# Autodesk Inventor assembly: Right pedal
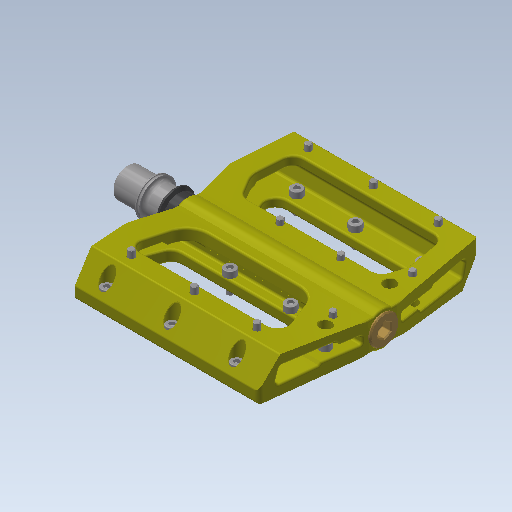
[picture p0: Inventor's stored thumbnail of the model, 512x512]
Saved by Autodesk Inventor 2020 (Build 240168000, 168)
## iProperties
Created: 2017-10
Part Number: Right pedal
Material: Ogólny
Document SubType Name: Assembly
Designer: Tomasz
Sending System: SolidWorks 2017
Last Author: Tomasz
Last Saved: 2017-11-20
Author: Tomasz
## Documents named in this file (3)
- C:\Users\bruno\Documents\1-Cours-2020-21\1STI2D-2020-21\IT\6. Antivol\Inventor-Antivol\INVENTOR 2018_Steel Hardtail B+\Right pedal.iam
- C:\Users\bruno\Documents\1-Cours-2020-21\1STI2D-2020-21\IT\6. Antivol\Inventor-Antivol\INVENTOR 2018_Steel Hardtail B+\Kopia Right pedal.iam^Right pedal.iam
- C:\Users\bruno\Documents\1-Cours-2020-21\1STI2D-2020-21\IT\6. Antivol\Inventor-Antivol\INVENTOR 2018_Steel Hardtail B+\686-2RS bearing.iam
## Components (3 placed, 2 different names)
1. Kopia Right pedal.iam^Right pedal:1 [sub-assembly]
2. 686-2RS bearing:1 [sub-assembly]
3. 686-2RS bearing:2 [sub-assembly]
